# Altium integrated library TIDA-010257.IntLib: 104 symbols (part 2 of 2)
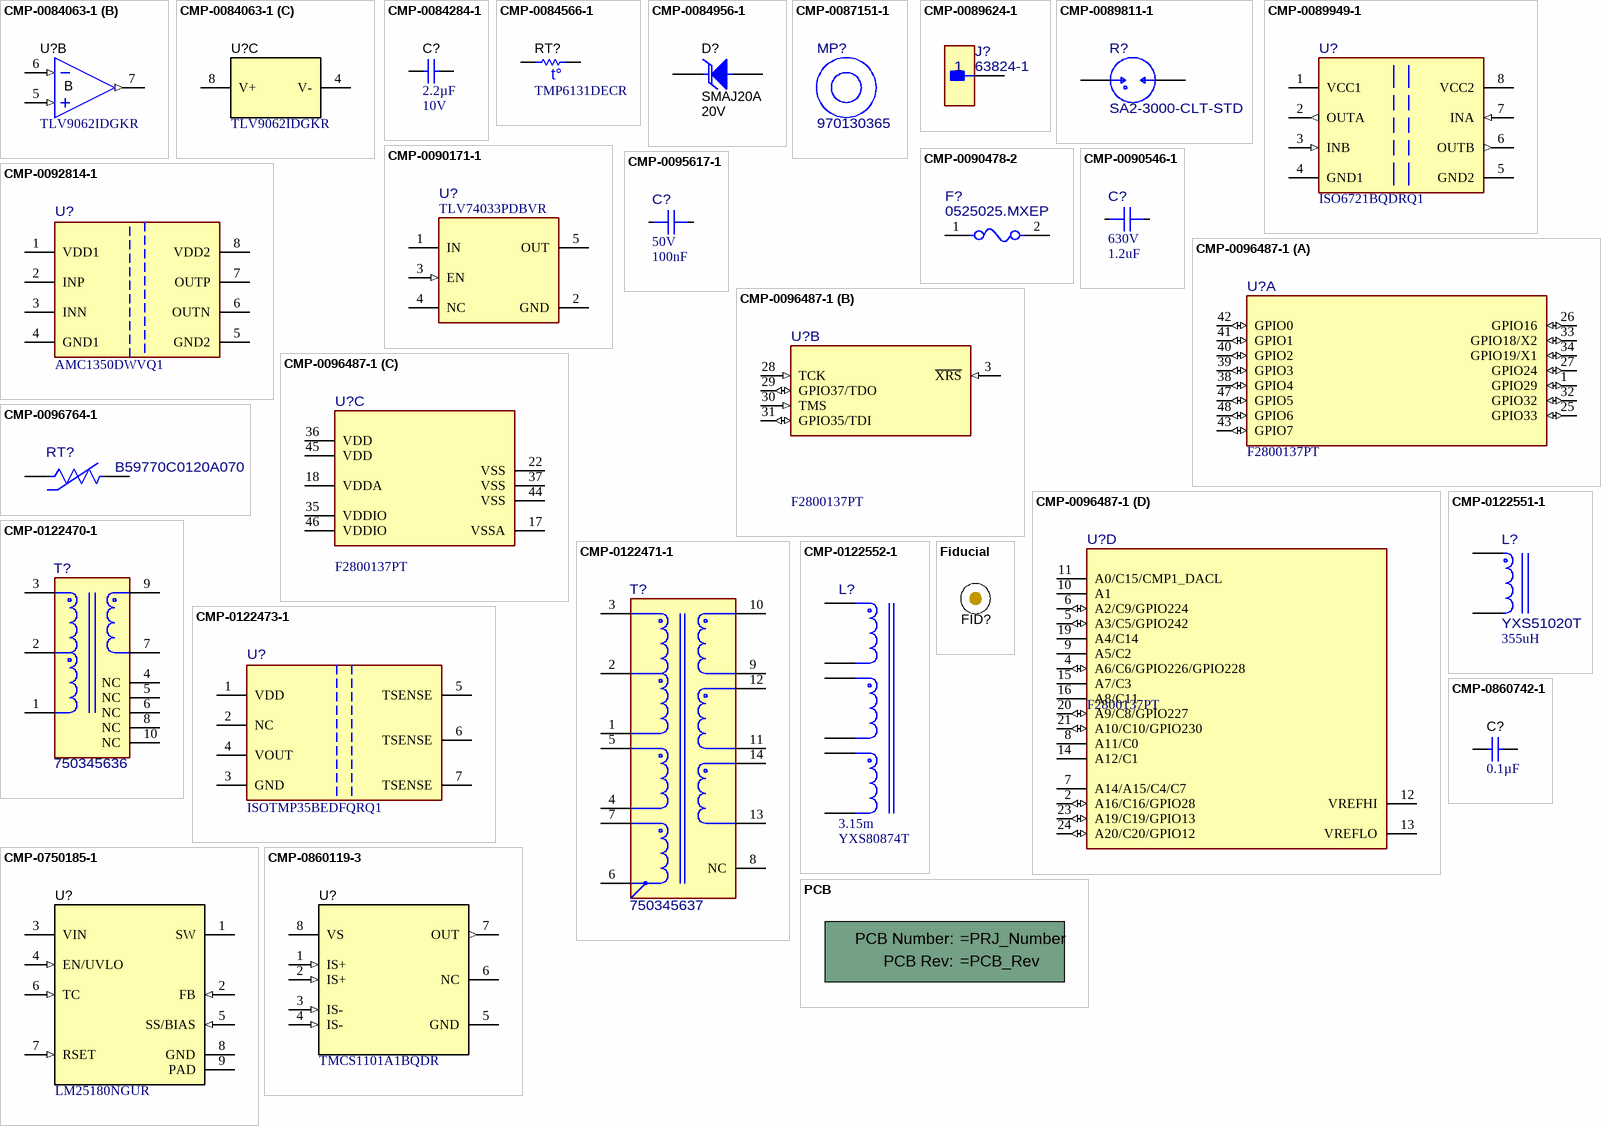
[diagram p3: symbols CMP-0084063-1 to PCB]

## CMP-0122473-1
designator U?, comment ISOTMP35BEDFQRQ1
Automotive ±1.5°C, 3-kVRMS Isolated Temperature Sensor With Analog Output With < 2 Seconds Response Time and 500VRMS Working Voltage; Manufacturer: Texas Instruments; SizeZ_mm: 1.75mm; AEC Qualified: Yes; AEC Grade: Grade 0; Max Supply Voltage: 5.5V; Min Supply Voltage: 2.3V; Operating Supply Current: 10uA; Sensor Output: Analog Voltage; Standoff Height: 0.11mm; TaMax_C: +150°C; TaMin_C: -40°C; TJmax_C: +155°C
footprint DFQ0007A-MFG
pins: 1 VDD (power), 2 NC, 3 GND (power), 4 VOUT, 5 TSENSE, 6 TSENSE, 7 TSENSE

## CMP-0122551-1
designator L?, comment YXS51020T  value 355uH
PFC INDUCTANCE 350uH 31A; Manufacturer: YAXIN ELECTRONICS; AEC Qualified: No; DCR_ohm: 25m; Ind_H: 355µH; SizeZ_mm: 60mm; Test Frequency: 100kHz; Tolerance_%: 12%
footprint FP-YXS51020T_PTH_IND_58MM0_70MM0-MFG
pins: 1, 2

## CMP-0122552-1
designator L?, comment DCR_ohm: 3.15m  (hidden comment: YXS80874T)
3 PHASES COMMON MODE CHOKE; Manufacturer: YAXIN ELECTRONICS; SizeZ_mm: 66mm; AEC Qualified: No
footprint FP-YXS80874T_PTH_CMC_66MM0_56MM0-MFG
pins: 1, 2, 3, 4, 5, 6

## CMP-0750185-1
designator U?, comment LM25180NGUR
LM25180 42-VIN PSR Flyback DC/DC Converter With 65-V, 1.5-A Integrated Power MOSFET, NGU0008C (WSON-8); Alternate Manufacturer: Texas Instruments; Alternate PartNumber: LM25180NGUT; CompType: IC; SizeArea_mm2: 16; AEC Qualified: N; SizeAreaWB_mm2: 25; AEC Category: Q200; SizeX_mm: 4; SizeZ_mm: 0.8
footprint NGU0008C (SON, 8-Leads, Body 4x4mm, Pitch 0.8mm)
pins: 1 SW (power), 2 FB (in), 3 VIN (power), 4 EN/UVLO (in), 5 SS/BIAS (in), 6 TC (in), 7 RSET (in), 8 GND (power), 9 PAD (power)

## CMP-0860119-3
designator U?, comment TMCS1101A1BQDR
Precision Isolated Current Sense Monitor With External Reference, D0008A (SOIC-8); Alternate Manufacturer: Texas Instruments; AEC Category: Q200; SizeArea_mm2: 30.38; AEC Qualified: N; SizeAreaWB_mm2: 56.58; SizeZ_mm: 1.75; CompType: IC; SizeX_mm: 4.9; SizeY_mm: 6.2
footprint D0008A_N (SOIC, 8-Leads, Body 4.9x3.9mm, Pitch 1.27mm, IPC Medium Density)
footprint D0008A_M (SOIC, 8-Leads, Body 4.9x3.9mm, Pitch 1.27mm, IPC Low Density)
footprint D0008A_L (SOIC, 8-Leads, Body 4.9x3.9mm, Pitch 1.27mm, IPC High Density)
pins: 1 IS+ (in), 2 IS+ (in), 3 IS- (in), 4 IS- (in), 5 GND (power), 6 NC, 7 OUT (out), 8 VS (power)

## CMP-0860742-1
designator C?, comment ValueDisplayed: 0.1µF  (hidden comment: 890334025017)
CAP, Film, 0.1 µF, 310 VAC/ VDC,+/- 10%, TH; Manufacturer: Wurth Elektronik; Manufacturer: Wurth Electronics; VAC: 310; SizeZ_mm: 12.5; Cap_F: 100nF; Polarized: N; SizeArea_mm2: 108; SizeX_mm: 18; TaMax_C: 105°C; SizeAreaWB_mm2: 160; Value: 0.1uF; CompType: Capacitor; Cap_Case: 18x6x12mm; TaMin_C: -40°C; AEC Category: Q200; SizeY_mm: 6
footprint WCAP-FTXX_P15PL20_1800x600 (TH, 2-Leads, Body 18x6mm)
pins: 1, 2

## Fiducial
designator FID?  (value not drawn)
Fiducial mark.  There is nothing to buy or mount.; SymbolCreator: codlsc
footprint Fiducial10-30
footprint Fiducial10-20
footprint Fiducial15-30
footprint Fiducial20-40
footprint Fiducial6.4-20

## PCB
designator MCU?, comment Printed Circuit Board of the Design  (value not drawn)  (mechanical)
Printed Circuit Board; Manufacturer: Any; PartNumber: MCU011; SymbolCreator: a0412235; CompType: PCB
1 alternate drawing of the same symbol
